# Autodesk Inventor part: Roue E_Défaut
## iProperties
Shininess: 64.0
Length Units: 11269
Angle Units: 11279
Time Units: 11290
Mass Units: 11283
Length Display Precision: 3
Angle Display Precision: 2
Compacted: True
Part Number: Roue E_Défaut
Document SubType Name: Modeling
Created: 2006-01
Material: Par défaut
Designer: Fricot
Density: 0.0
Volumn: 0.0
Area: 0.0
PropertySet Name: Model Information
Control State: 0
Master: False
Checked Out: False
Author: Fricot
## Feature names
1. Base1
